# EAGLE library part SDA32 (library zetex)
DIODE ARRAY
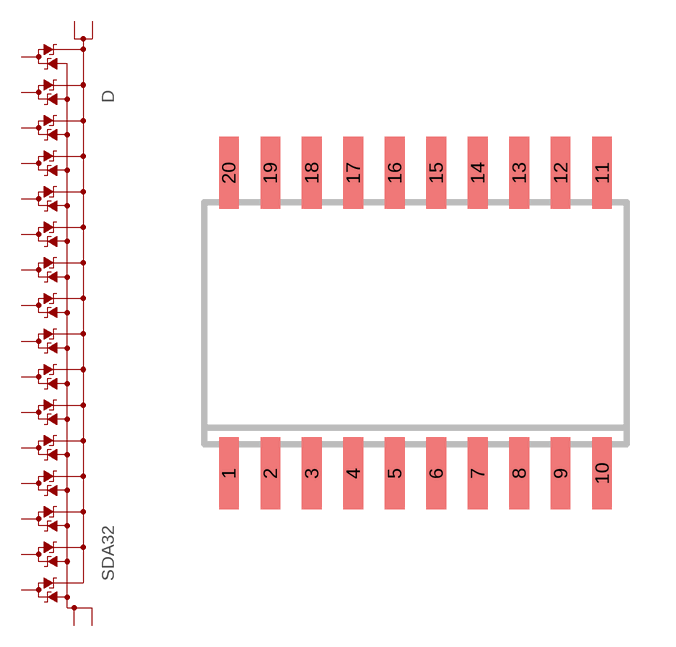
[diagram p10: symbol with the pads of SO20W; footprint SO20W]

Designator prefix D

## SDA32 (OC_FARNELL: 1749275; OC_NEWARK: unknown)  [SO20W]
1  V+  pas
2  D01  pas
3  D02  pas
4  D03  pas
5  D04  pas
6  D05  pas
7  D06  pas
8  D07  pas
9  D08  pas
10  V-  pas
11  V-1  pas
12  D09  pas
13  D10  pas
14  D11  pas
15  D12  pas
16  D13  pas
17  D14  pas
18  D15  pas
19  D16  pas
20  V+1  pas

## Footprint SO20W (pad centres in mm)
SMALL OUTLINE INTEGRATED CIRCUIT wide body 7.5 mm/JEDEC MS-013AC
smd 0.6 x 2.2: 1 -5.715,-4.6; 2 -4.445,-4.6; 3 -3.175,-4.6; 4 -1.905,-4.6; 5 -0.635,-4.6; 6 0.635,-4.6; 7 1.905,-4.6; 8 3.175,-4.6; 9 4.445,-4.6; 10 5.715,-4.6; 11 5.715,4.6; 12 4.445,4.6; 13 3.175,4.6; 14 1.905,4.6; 15 0.635,4.6; 16 -0.635,4.6; 17 -1.905,4.6; 18 -3.175,4.6; 19 -4.445,4.6; 20 -5.715,4.6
